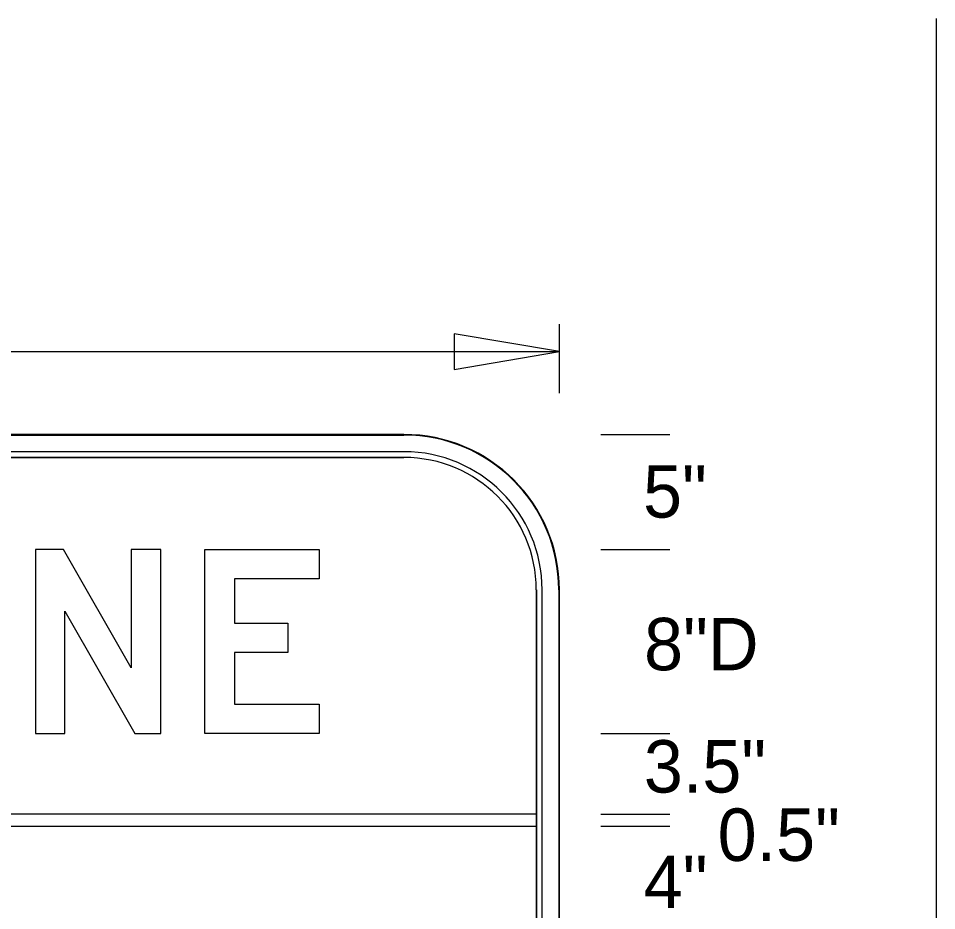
# Model space of a CAD drawing. Extents: x 0 to 770, y 0 to 495.
# Drawn here: x 516.2 to 577.5, y 435.4 to 495 of the extents above; entities that cross this region are included whole.
import ezdxf

# ---------------------------------------------------------------- set-up
doc = ezdxf.new("R2010")
doc.units = 0
for name, color, linetype in [('Dimension', 7, 'Continuous'), ('GSBWFill', 7, 'Continuous'), ('GSColorFill', 7, 'Continuous'), ('GSDims', 7, 'Continuous'), ('GSOutline', 7, 'Continuous'), ('SheetLines_dp', 7, 'Continuous'), ('TextStructures', 7, 'Continuous')]:
    doc.layers.add(name, color=color, linetype=linetype)

msp = doc.modelspace()

# ---------------------------------------------------------------- linework, layer by layer
at = {"layer": 'Dimension'}
msp.add_lwpolyline([(552.311, 472.741), (545.294, 473.93), (545.294, 471.552)], close=True, dxfattribs=at)
at = {"layer": 'GSBWFill'}
for p, q in [((541.937, 467.209), (415.154, 467.209)), ((541.937, 466.056), (415.154, 466.056)), ((415.154, 465.672), (541.937, 465.672)), ((550.774, 456.835), (550.774, 403.817)), ((551.158, 403.817), (551.158, 456.835)), ((552.311, 403.817), (552.311, 456.835)), ((550.774, 441.852), (406.317, 441.852)), ((550.774, 441.053), (550.774, 441.852)), ((406.317, 441.053), (550.774, 441.053))]:
    msp.add_line(p, q, dxfattribs=at)
for points in [[(525.694, 447.23), (525.694, 459.525), (523.727, 459.525), (523.727, 451.626), (519.213, 459.525), (517.334, 459.525), (517.334, 447.23), (519.301, 447.23), (519.301, 455.406), (523.973, 447.23)], [(536.267, 457.558), (530.611, 457.558), (530.611, 454.607), (534.186, 454.607), (534.186, 452.64), (530.611, 452.64), (530.611, 449.198), (536.267, 449.198), (536.267, 447.23), (528.644, 447.23), (528.644, 459.525), (536.267, 459.525)]]:
    msp.add_lwpolyline(points, close=True, dxfattribs=at)
for radius in [10.373, 9.221, 8.836]:
    msp.add_arc((541.937, 456.835), radius, 0, 90, dxfattribs=at)
at = {"layer": 'GSColorFill'}
for p, q in [((541.937, 467.209), (415.154, 467.209)), ((541.937, 467.209), (415.154, 467.209)), ((415.154, 467.17), (541.937, 467.17)), ((541.937, 466.056), (415.154, 466.056)), ((415.154, 465.672), (541.937, 465.672)), ((550.774, 456.835), (550.774, 403.817)), ((551.158, 403.817), (551.158, 456.835)), ((552.272, 456.835), (552.272, 403.817)), ((552.311, 403.817), (552.311, 456.835)), ((552.311, 403.817), (552.311, 456.835)), ((550.774, 441.852), (406.317, 441.852)), ((550.774, 441.053), (550.774, 441.852)), ((406.317, 441.053), (550.774, 441.053))]:
    msp.add_line(p, q, dxfattribs=at)
for points in [[(525.694, 447.23), (525.694, 459.525), (523.727, 459.525), (523.727, 451.626), (519.213, 459.525), (517.334, 459.525), (517.334, 447.23), (519.301, 447.23), (519.301, 455.406), (523.973, 447.23)], [(536.267, 457.558), (530.611, 457.558), (530.611, 454.607), (534.186, 454.607), (534.186, 452.64), (530.611, 452.64), (530.611, 449.198), (536.267, 449.198), (536.267, 447.23), (528.644, 447.23), (528.644, 459.525), (536.267, 459.525)]]:
    msp.add_lwpolyline(points, close=True, dxfattribs=at)
for radius in [10.373, 10.373, 10.335, 9.221, 8.836]:
    msp.add_arc((541.937, 456.835), radius, 0, 90, dxfattribs=at)
at = {"layer": 'GSDims'}
for p, q in [((552.311, 469.975), (552.311, 474.585)), ((404.78, 472.741), (552.311, 472.741)), ((555.077, 467.209), (559.687, 467.209)), ((555.077, 459.525), (559.687, 459.525)), ((555.077, 459.525), (559.687, 459.525)), ((555.077, 447.23), (559.687, 447.23)), ((555.077, 447.23), (559.687, 447.23)), ((555.077, 441.852), (559.687, 441.852)), ((555.077, 441.852), (559.687, 441.852)), ((555.077, 441.053), (559.687, 441.053)), ((555.077, 441.053), (559.687, 441.053))]:
    msp.add_line(p, q, dxfattribs=at)
at = {"layer": 'GSOutline'}
for p, q in [((541.937, 467.209), (415.154, 467.209)), ((541.937, 466.056), (415.154, 466.056)), ((541.937, 465.672), (415.154, 465.672)), ((550.774, 403.817), (550.774, 456.835)), ((551.158, 403.817), (551.158, 456.835)), ((552.311, 403.817), (552.311, 456.835)), ((550.774, 441.852), (406.317, 441.852)), ((550.774, 441.053), (550.774, 441.852)), ((406.317, 441.053), (550.774, 441.053))]:
    msp.add_line(p, q, dxfattribs=at)
for points in [[(525.694, 447.23), (525.694, 459.525), (523.727, 459.525), (523.727, 451.626), (519.213, 459.525), (517.334, 459.525), (517.334, 447.23), (519.301, 447.23), (519.301, 455.406), (523.973, 447.23)], [(536.267, 457.558), (530.611, 457.558), (530.611, 454.607), (534.186, 454.607), (534.186, 452.64), (530.611, 452.64), (530.611, 449.198), (536.267, 449.198), (536.267, 447.23), (528.644, 447.23), (528.644, 459.525), (536.267, 459.525)]]:
    msp.add_lwpolyline(points, close=True, dxfattribs=at)
for radius in [10.373, 9.221, 8.836]:
    msp.add_arc((541.937, 456.835), radius, 0, 90, dxfattribs=at)
at = {"layer": 'SheetLines_dp'}
msp.add_line((577.501, 0), (577.501, 495), dxfattribs=at)

# ---------------------------------------------------------------- texts
at = {"layer": 'TextStructures'}
for s, p in [('5"', (557.898, 461.656)), ('8"D', (557.967, 451.46)), ('3.5"', (557.952, 443.292)), ('0.5"', (562.879, 438.728)), ('4"', (557.942, 435.58))]:
    msp.add_text(s, height=3.5, dxfattribs=at).set_placement(p)

doc.saveas('drawing.dxf')
